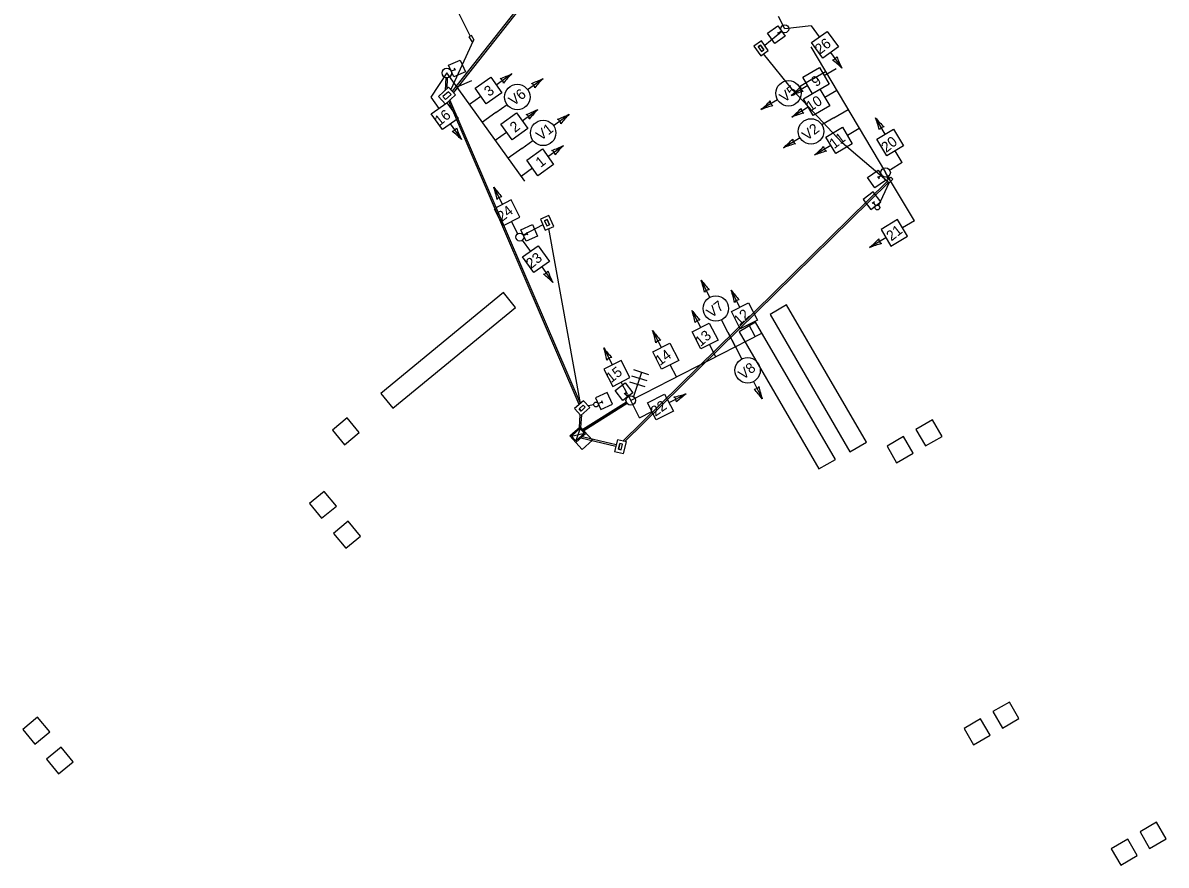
# Model space of a CAD drawing. Extents: x 995948 to 996893, y 1982239 to 1983420.
# Drawn here: x 996486.3 to 996846.1, y 1982238.6 to 1982503.8 of the extents above; entities that cross this region are included whole.
import ezdxf

# ---------------------------------------------------------------- set-up
doc = ezdxf.new("R2010")
doc.units = 0
for name, color, linetype in [('S_CURB', 7, 'Continuous'), ('S_DRIVEWAY', 7, 'Continuous'), ('S_EDGE_PAVEMENT', 7, 'Continuous'), ('S_PARKING', 7, 'Continuous'), ('S_PAVEMENT_CROWN', 7, 'Continuous'), ('S_SHOULDER', 7, 'Continuous'), ('S_SIDEWALK', 7, 'Continuous'), ('S_WALL', 7, 'Continuous')]:
    doc.layers.add(name, color=color, linetype=linetype)

msp = doc.modelspace()

# ---------------------------------------------------------------- linework, layer by layer
at = {"layer": 'S_CURB'}
for p, q in [((996658.48, 1982373.75), (996661.69, 1982376.65)), ((996665.53, 1982372.38), (996661.69, 1982376.65)), ((996662.32, 1982369.49), (996658.48, 1982373.75)), ((996658.94, 1982373.73), (996661.67, 1982376.18)), ((996660.33, 1982372.18), (996658.94, 1982373.73)), ((996658.96, 1982373.74), (996663.06, 1982374.64)), ((996660.31, 1982371.72), (996663.53, 1982374.61)), ((996661.67, 1982376.18), (996660.33, 1982372.19)), ((996660.33, 1982372.18), (996663.06, 1982374.64)), ((996663.06, 1982374.64), (996661.67, 1982376.18)), ((996662.32, 1982369.49), (996665.53, 1982372.38))]:
    msp.add_line(p, q, dxfattribs=at)
at = {"layer": 'S_DRIVEWAY'}
for p, q in [((996682.34, 1982559.39), (996621.37, 1982482.35)), ((996682.97, 1982559.38), (996621.8, 1982481.88)), ((996621.13, 1982511.73), (996627.07, 1982499.65)), ((996725.15, 1982501.15), (996719.78, 1982496.69)), ((996627.98, 1982498.16), (996620.96, 1982482.8)), ((996619.37, 1982486.58), (996619.15, 1982482.55)), ((996619.87, 1982486.55), (996619.68, 1982483.03)), ((996661.4, 1982383.66), (996620.32, 1982479.2)), ((996661.79, 1982384.01), (996620.71, 1982479.55)), ((996758.36, 1982453.88), (996675.15, 1982372.13)), ((996758.71, 1982453.52), (996675.72, 1982371.99)), ((996758.85, 1982453.37), (996755.56, 1982446.34)), ((996758.26, 1982455.25), (996758.66, 1982454.46)), ((996758.71, 1982455.48), (996759.04, 1982454.82)), ((996649.96, 1982440.21), (996643.79, 1982436.96)), ((996661.81, 1982384.02), (996651.81, 1982439.06)), ((996676.23, 1982384.36), (996662.48, 1982375.78)), ((996676.34, 1982384.14), (996662.65, 1982375.59)), ((996676.49, 1982383.94), (996662.82, 1982375.4)), ((996661.43, 1982376.42), (996661.67, 1982380.45)), ((996661.93, 1982376.39), (996662.17, 1982380.41)), ((996665.94, 1982383.54), (996664.17, 1982383.28)), ((996672.91, 1982370.48), (996661.86, 1982373.11)), ((996673.02, 1982370.97), (996662.31, 1982373.52))]:
    msp.add_line(p, q, dxfattribs=at)
msp.add_lwpolyline([(996758.22, 1982454.03), (996744.12, 1982466.06), (996728.69, 1982482.57), (996719.38, 1982494.02)], dxfattribs=at)
at = {"layer": 'S_EDGE_PAVEMENT'}
for p, q in [((996734.34, 1982496.24), (996757.83, 1982456.69)), ((996644.28, 1982453.98), (996619.7, 1982488.04)), ((996718.54, 1982405.93), (996677.61, 1982384.93))]:
    msp.add_line(p, q, dxfattribs=at)
for centre, radius in [((996726.11, 1982501.95), 1.25), ((996619.7, 1982488.04), 1.5), ((996757.83, 1982456.69), 1.5), ((996755.24, 1982445.66), 0.75), ((996642.69, 1982436.37), 1.25), ((996666.68, 1982383.65), 0.75), ((996677.61, 1982384.93), 1.5)]:
    msp.add_circle(centre, radius, dxfattribs=at)
at = {"layer": 'S_PARKING'}
for points in [[(996637.55, 1982418.87), (996598.91, 1982387.13), (996602.72, 1982382.5), (996641.36, 1982414.23)], [(996751.77, 1982371.76), (996726.65, 1982415), (996721.46, 1982411.98), (996746.58, 1982368.75)], [(996742.03, 1982366.37), (996716.91, 1982409.6), (996711.72, 1982406.59), (996736.84, 1982363.36)], [(996588.34, 1982379.44), (996583.7, 1982375.63), (996587.51, 1982370.99), (996592.15, 1982374.8)], [(996767.39, 1982375.81), (996770.4, 1982370.62), (996775.59, 1982373.63), (996772.58, 1982378.82)], [(996758.3, 1982370.52), (996761.31, 1982365.34), (996766.5, 1982368.35), (996763.49, 1982373.54)], [(996581.14, 1982356.27), (996576.51, 1982352.46), (996580.31, 1982347.82), (996584.95, 1982351.63)], [(996588.7, 1982346.88), (996584.06, 1982343.07), (996587.87, 1982338.44), (996592.51, 1982342.24)], [(996791.62, 1982286.95), (996794.64, 1982281.77), (996799.82, 1982284.78), (996796.81, 1982289.97)], [(996490.9, 1982285.18), (996486.26, 1982281.37), (996490.07, 1982276.74), (996494.7, 1982280.55)], [(996782.53, 1982281.67), (996785.55, 1982276.48), (996790.73, 1982279.5), (996787.72, 1982284.69)], [(996498.31, 1982275.78), (996493.67, 1982271.98), (996497.48, 1982267.34), (996502.12, 1982271.15)], [(996837.93, 1982249.1), (996840.95, 1982243.91), (996846.14, 1982246.92), (996843.12, 1982252.11)], [(996828.84, 1982243.81), (996831.86, 1982238.63), (996837.05, 1982241.64), (996834.03, 1982246.83)]]:
    msp.add_lwpolyline(points, close=True, dxfattribs=at)
at = {"layer": 'S_PAVEMENT_CROWN'}
for p, q in [((996726.11, 1982501.95), (996724.12, 1982505.82)), ((996734.42, 1982502.9), (996726.11, 1982501.95)), ((996734.42, 1982502.9), (996736.96, 1982499.37)), ((996740.52, 1982494.46), (996744.05, 1982489.56)), ((996742.27, 1982489.38), (996738.53, 1982487.17)), ((996619.7, 1982488.04), (996614.7, 1982480.42)), ((996635.29, 1982484.3), (996640.19, 1982487.83)), ((996645.15, 1982482.81), (996650.07, 1982486.35)), ((996734.41, 1982485.88), (996730.69, 1982483.67)), ((996733.32, 1982484.06), (996728.12, 1982480.98)), ((996742.45, 1982482.54), (996738.71, 1982480.33)), ((996614.7, 1982480.42), (996617.24, 1982476.89)), ((996626.84, 1982478.21), (996630.37, 1982480.75)), ((996635.14, 1982475.6), (996638.66, 1982478.13)), ((996723.81, 1982479.59), (996718.59, 1982476.5)), ((996643.43, 1982472.99), (996648.33, 1982476.51)), ((996653.29, 1982471.49), (996658.21, 1982475.04)), ((996733.5, 1982477.23), (996728.3, 1982474.15)), ((996741.51, 1982473.89), (996737.79, 1982471.68)), ((996757.72, 1982468.74), (996754.62, 1982473.93)), ((996620.8, 1982471.98), (996624.33, 1982467.08)), ((996749.55, 1982470.55), (996745.81, 1982468.33)), ((996634.98, 1982466.9), (996638.51, 1982469.44)), ((996643.28, 1982464.29), (996646.79, 1982466.82)), ((996730.91, 1982467.6), (996725.69, 1982464.51)), ((996651.54, 1982461.7), (996656.45, 1982465.23)), ((996740.6, 1982465.24), (996735.4, 1982462.16)), ((996763.07, 1982459.81), (996760.84, 1982463.54)), ((996763.07, 1982459.81), (996759.33, 1982457.58)), ((996643.11, 1982455.6), (996646.64, 1982458.14)), ((996766.89, 1982441.48), (996757.83, 1982456.69)), ((996637.28, 1982446.7), (996634.51, 1982452.07)), ((996766.89, 1982441.48), (996763.16, 1982439.25)), ((996642.02, 1982437.43), (996640.03, 1982441.3)), ((996643.47, 1982435.4), (996646.01, 1982431.87)), ((996757.95, 1982436.16), (996752.76, 1982433.06)), ((996649.57, 1982426.96), (996653.1, 1982422.06)), ((996702.55, 1982417.44), (996699.77, 1982422.83)), ((996711.99, 1982414.27), (996709.24, 1982419.65)), ((996699.62, 1982407.92), (996696.87, 1982413.3)), ((996708.19, 1982406.48), (996706.21, 1982410.33)), ((996687.25, 1982401.57), (996684.49, 1982406.95)), ((996716.76, 1982405.02), (996714.78, 1982408.88)), ((996704.39, 1982398.67), (996702.41, 1982402.54)), ((996710.58, 1982401.83), (996712.56, 1982397.98)), ((996671.87, 1982396.13), (996669.11, 1982401.5)), ((996692.01, 1982392.32), (996690.03, 1982396.19)), ((996676.62, 1982386.87), (996674.63, 1982390.73)), ((996716.21, 1982390.86), (996718.98, 1982385.47)), ((996676.62, 1982386.87), (996677.61, 1982384.93)), ((996680.4, 1982379.51), (996677.61, 1982384.93)), ((996689.66, 1982384.27), (996695.04, 1982387.02)), ((996680.4, 1982379.51), (996684.27, 1982381.49))]:
    msp.add_line(p, q, dxfattribs=at)
for points in [[(996734.51, 1982497.61), (996739.43, 1982501.15), (996742.97, 1982496.23), (996738.05, 1982492.68)], [(996736.99, 1982489.76), (996740.08, 1982484.54), (996734.86, 1982481.45), (996731.77, 1982486.67)], [(996632.14, 1982478.29), (996628.6, 1982483.21), (996633.52, 1982486.75), (996637.06, 1982481.83)], [(996737.16, 1982482.93), (996740.25, 1982477.72), (996735.04, 1982474.63), (996731.95, 1982479.85)], [(996614.79, 1982475.13), (996619.72, 1982478.67), (996623.26, 1982473.75), (996618.33, 1982470.21)], [(996640.28, 1982466.98), (996636.74, 1982471.9), (996641.66, 1982475.44), (996645.2, 1982470.52)], [(996744.26, 1982470.94), (996747.35, 1982465.72), (996742.14, 1982462.64), (996739.05, 1982467.85)], [(996763.43, 1982465.09), (996758.22, 1982461.98), (996755.12, 1982467.19), (996760.33, 1982470.3)], [(996648.4, 1982455.69), (996644.86, 1982460.61), (996649.78, 1982464.15), (996653.32, 1982459.23)], [(996637.35, 1982439.91), (996642.74, 1982442.69), (996639.97, 1982448.08), (996634.57, 1982445.31)], [(996764.71, 1982436.66), (996761.6, 1982441.87), (996756.39, 1982438.75), (996759.51, 1982433.55)], [(996643.56, 1982430.11), (996648.48, 1982433.65), (996652.02, 1982428.73), (996647.1, 1982425.19)], [(996717.47, 1982410.26), (996712.07, 1982407.49), (996709.3, 1982412.89), (996714.7, 1982415.66)], [(996705.09, 1982403.91), (996699.69, 1982401.15), (996696.93, 1982406.54), (996702.33, 1982409.31)], [(996692.72, 1982397.56), (996687.32, 1982394.8), (996684.56, 1982400.19), (996689.95, 1982402.96)], [(996671.95, 1982389.35), (996677.34, 1982392.13), (996674.56, 1982397.52), (996669.17, 1982394.74)], [(996685.65, 1982378.8), (996682.89, 1982384.2), (996688.28, 1982386.96), (996691.04, 1982381.56)]]:
    msp.add_lwpolyline(points, close=True, dxfattribs=at)
for centre in [(996727.25, 1982481.63), (996641.9, 1982480.47), (996650.04, 1982469.16), (996734.35, 1982469.64), (996704.38, 1982413.88), (996714.38, 1982394.42)]:
    msp.add_circle(centre, 4, dxfattribs=at)
for centre, radius, start, end in [((996740.97, 1982493.83), 1.63, 273.8828, 337.5774), ((996722.97, 1982468.96), 29.47, 44.3384, 52.0765), ((996770.28, 1982502.99), 29.47, 199.3837, 207.1218), ((996626.76, 1982514.06), 29.47, 289.381, 297.1192), ((996635.92, 1982484.75), 1.63, 3.8802, 67.5748), ((996660.79, 1982466.75), 29.47, 134.3358, 142.0739), ((996636.62, 1982512.57), 29.47, 289.4116, 297.1497), ((996645.8, 1982483.27), 1.63, 3.9107, 67.6053), ((996670.68, 1982465.28), 29.47, 134.3663, 142.1045), ((996709.48, 1982503.81), 29.47, 309.236, 316.9741), ((996739.17, 1982453.66), 29.47, 104.2813, 112.0194), ((996732.65, 1982483.66), 1.63, 178.7804, 242.475), ((996699.94, 1982499.32), 29.47, 309.2666, 317.0047), ((996729.65, 1982449.19), 29.47, 104.3118, 112.05), ((996723.12, 1982479.19), 1.63, 178.811, 242.5056), ((996634.89, 1982502.75), 29.47, 289.381, 297.1192), ((996644.05, 1982473.44), 1.63, 3.8802, 67.5748), ((996668.93, 1982455.43), 29.47, 134.3358, 142.0739), ((996644.76, 1982501.26), 29.47, 289.4116, 297.1497), ((996678.82, 1982453.97), 29.47, 134.3663, 142.1045), ((996709.66, 1982496.98), 29.47, 309.236, 316.9741), ((996739.35, 1982446.83), 29.47, 104.2813, 112.0194), ((996732.83, 1982476.84), 1.63, 178.7804, 242.475), ((996777.4, 1982492.64), 29.47, 219.4006, 227.1387), ((996727.34, 1982462.8), 29.47, 14.4459, 22.184), ((996621.25, 1982471.35), 1.63, 273.8828, 337.5774), ((996650.56, 1982480.51), 29.47, 199.3837, 207.1218), ((996653.93, 1982471.96), 1.63, 3.9107, 67.6053), ((996757.32, 1982469.41), 1.63, 88.945, 152.6396), ((996603.25, 1982446.48), 29.47, 44.3384, 52.0765), ((996707.03, 1982487.33), 29.47, 309.2666, 317.0047), ((996730.22, 1982467.2), 1.63, 178.811, 242.5056), ((996643.01, 1982491.46), 29.47, 289.381, 297.1192), ((996652.17, 1982462.15), 1.63, 3.8802, 67.5748), ((996677.05, 1982444.15), 29.47, 134.3358, 142.0739), ((996736.75, 1982437.19), 29.47, 104.3118, 112.05), ((996716.76, 1982484.99), 29.47, 309.236, 316.9741), ((996746.45, 1982434.84), 29.47, 104.2813, 112.0194), ((996739.93, 1982464.84), 1.63, 178.7804, 242.475), ((996606.58, 1982442.65), 29.47, 10.8925, 18.6306), ((996658.4, 1982469.33), 29.47, 215.8473, 223.5854), ((996636.92, 1982447.38), 1.63, 85.3916, 149.0863), ((996734.02, 1982455.81), 29.47, 309.4816, 317.2197), ((996763.93, 1982405.78), 29.47, 104.5268, 112.2649), ((996757.28, 1982435.76), 1.63, 179.0259, 242.7206), ((996650.02, 1982426.33), 1.63, 273.8828, 337.5774), ((996632.02, 1982401.46), 29.47, 44.3384, 52.0765), ((996679.33, 1982435.5), 29.47, 199.3837, 207.1218), ((996723.66, 1982440.09), 29.47, 215.8477, 223.5859), ((996671.84, 1982413.42), 29.47, 10.893, 18.6311), ((996702.18, 1982418.15), 1.63, 85.3921, 149.0867), ((996733.17, 1982436.86), 29.47, 215.7298, 223.468), ((996681.29, 1982410.29), 29.47, 10.7751, 18.5132), ((996711.64, 1982414.96), 1.63, 85.2742, 148.9688), ((996720.79, 1982430.51), 29.47, 215.7298, 223.468), ((996668.92, 1982403.94), 29.47, 10.7751, 18.5132), ((996699.27, 1982408.61), 1.63, 85.2742, 148.9688), ((996708.42, 1982424.16), 29.47, 215.7298, 223.468), ((996656.55, 1982397.59), 29.47, 10.7751, 18.5132), ((996686.9, 1982402.26), 1.63, 85.2742, 148.9688), ((996641.18, 1982392.09), 29.47, 10.8925, 18.6306), ((996693, 1982418.76), 29.47, 215.8473, 223.5854), ((996671.52, 1982396.82), 1.63, 85.3916, 149.0863), ((996716.57, 1982390.15), 1.63, 265.3183, 329.0129), ((996695.07, 1982368.24), 29.47, 35.7739, 43.512), ((996746.92, 1982394.85), 29.47, 190.8192, 198.5573), ((996685.7, 1982414.98), 29.47, 280.7306, 288.4687), ((996690.35, 1982384.62), 1.63, 355.2297, 58.9243), ((996712.23, 1982363.08), 29.47, 125.6853, 133.4234)]:
    msp.add_arc(centre, radius, start, end, dxfattribs=at)
at = {"layer": 'S_SHOULDER'}
msp.add_line((996623.01, 1982483.69), (996627.58, 1982485.72), dxfattribs=at)
for points in [[(996726.23, 1982499.6), (996722.96, 1982497.3), (996720.66, 1982500.58), (996723.94, 1982502.88)], [(996620.26, 1982490.48), (996623.92, 1982492.1), (996625.54, 1982488.45), (996621.89, 1982486.82)], [(996757.75, 1982454.19), (996754.47, 1982451.89), (996752.18, 1982455.17), (996755.45, 1982457.47)], [(996756.37, 1982447.48), (996753.92, 1982450.64), (996750.75, 1982448.19), (996753.2, 1982445.03)], [(996643.02, 1982438.7), (996646.67, 1982440.33), (996648.3, 1982436.67), (996644.64, 1982435.05)], [(996668.18, 1982382.13), (996671.84, 1982383.75), (996670.21, 1982387.41), (996666.56, 1982385.78)], [(996675.11, 1982384.89), (996672.66, 1982388.06), (996675.83, 1982390.51), (996678.28, 1982387.34)]]:
    msp.add_lwpolyline(points, close=True, dxfattribs=at)
at = {"layer": 'S_SIDEWALK'}
for p, q in [((996627.46, 1982499.89), (996626.68, 1982499.41)), ((996626.68, 1982499.41), (996627.58, 1982497.92)), ((996628.37, 1982498.39), (996627.46, 1982499.89)), ((996723.76, 1982500.84), (996724.26, 1982500.12)), ((996725.09, 1982501.24), (996724.01, 1982500.48)), ((996627.58, 1982497.92), (996628.37, 1982498.39)), ((996718.75, 1982498.16), (996716.36, 1982496.48)), ((996716.36, 1982496.48), (996718.51, 1982493.41)), ((996717.75, 1982496.23), (996718.5, 1982496.76)), ((996718.5, 1982496.76), (996717.75, 1982496.23)), ((996717.75, 1982496.23), (996718.75, 1982494.8)), ((996717.75, 1982496.23), (996718.75, 1982494.8)), ((996718.5, 1982496.76), (996719.51, 1982495.33)), ((996719.51, 1982495.33), (996718.5, 1982496.76)), ((996720.9, 1982495.08), (996718.75, 1982498.16)), ((996718.51, 1982493.41), (996720.9, 1982495.08)), ((996718.75, 1982494.8), (996719.51, 1982495.33)), ((996718.75, 1982494.8), (996719.51, 1982495.33)), ((996621.07, 1982488.65), (996622.28, 1982489.18)), ((996622.45, 1982488.79), (996622.1, 1982489.58)), ((996734.41, 1982485.88), (996738.9, 1982488.54)), ((996620.27, 1982483.57), (996617.06, 1982480.66)), ((996620.2, 1982482.15), (996618.47, 1982480.59)), ((996619.25, 1982478.23), (996622.47, 1982481.14)), ((996619.32, 1982479.65), (996621.05, 1982481.21)), ((996621.05, 1982481.21), (996620.2, 1982482.15)), ((996622.47, 1982481.14), (996620.27, 1982483.57)), ((996617.06, 1982480.66), (996619.25, 1982478.23)), ((996618.47, 1982480.59), (996619.32, 1982479.65)), ((996635.14, 1982475.6), (996630.91, 1982472.55)), ((996741.51, 1982473.89), (996746, 1982476.55)), ((996643.28, 1982464.29), (996639.05, 1982461.24)), ((996756.6, 1982455.83), (996755.52, 1982455.07)), ((996755.27, 1982455.43), (996755.77, 1982454.71)), ((996759.48, 1982455.24), (996758.22, 1982454.03)), ((996758.22, 1982454.03), (996758.85, 1982453.37)), ((996758.85, 1982453.37), (996760.12, 1982454.58)), ((996760.12, 1982454.58), (996759.48, 1982455.24)), ((996753.63, 1982447.03), (996754.32, 1982447.56)), ((996754.78, 1982446.25), (996753.98, 1982447.29)), ((996651.84, 1982443.18), (996649.17, 1982441.99)), ((996649.17, 1982441.99), (996650.7, 1982438.56)), ((996650.49, 1982441.48), (996651.33, 1982441.86)), ((996651.33, 1982441.86), (996650.49, 1982441.48)), ((996650.49, 1982441.48), (996651.2, 1982439.88)), ((996650.49, 1982441.48), (996651.2, 1982439.88)), ((996651.33, 1982441.86), (996652.04, 1982440.26)), ((996652.04, 1982440.26), (996651.33, 1982441.86)), ((996653.36, 1982439.75), (996651.84, 1982443.18)), ((996645.21, 1982437.01), (996644.86, 1982437.81)), ((996650.7, 1982438.56), (996653.36, 1982439.75)), ((996651.2, 1982439.88), (996652.04, 1982440.26)), ((996651.2, 1982439.88), (996652.04, 1982440.26)), ((996643.83, 1982436.88), (996645.03, 1982437.41)), ((996708.19, 1982406.48), (996710.58, 1982401.84)), ((996710.58, 1982401.83), (996708.2, 1982406.47)), ((996676.23, 1982387.43), (996675.54, 1982386.89)), ((996662.73, 1982384.86), (996659.95, 1982382.35)), ((996664.69, 1982382.7), (996662.73, 1982384.86)), ((996667.37, 1982383.96), (996668.57, 1982384.49)), ((996668.39, 1982384.89), (996668.75, 1982384.09)), ((996676.69, 1982386.12), (996675.89, 1982387.16)), ((996659.95, 1982382.35), (996661.91, 1982380.18)), ((996661.37, 1982382.28), (996662.66, 1982383.45)), ((996662.66, 1982383.45), (996661.37, 1982382.28)), ((996661.98, 1982381.59), (996661.37, 1982382.28)), ((996661.37, 1982382.28), (996661.98, 1982381.59)), ((996661.91, 1982380.18), (996664.69, 1982382.7)), ((996661.98, 1982381.59), (996663.28, 1982382.77)), ((996661.98, 1982381.59), (996663.28, 1982382.77)), ((996663.28, 1982382.77), (996662.66, 1982383.45)), ((996663.28, 1982382.77), (996662.66, 1982383.45)), ((996673.4, 1982372.55), (996672.53, 1982368.9)), ((996676.24, 1982371.87), (996673.4, 1982372.55)), ((996673.73, 1982369.64), (996674.14, 1982371.34)), ((996674.14, 1982371.34), (996673.73, 1982369.64)), ((996674.63, 1982369.43), (996673.73, 1982369.64)), ((996673.73, 1982369.64), (996674.63, 1982369.43)), ((996675.04, 1982371.13), (996674.14, 1982371.34)), ((996675.04, 1982371.13), (996674.14, 1982371.34)), ((996674.63, 1982369.43), (996675.04, 1982371.13)), ((996674.63, 1982369.43), (996675.04, 1982371.13)), ((996675.37, 1982368.22), (996676.24, 1982371.87)), ((996672.53, 1982368.9), (996675.37, 1982368.22))]:
    msp.add_line(p, q, dxfattribs=at)
at = {"layer": 'S_WALL'}
for p, q in [((996682.73, 1982391.08), (996677.98, 1982392.63)), ((996680.97, 1982393.76), (996678.49, 1982386.15)), ((996683.35, 1982392.98), (996678.6, 1982394.53)), ((996682.11, 1982389.18), (996677.35, 1982390.73))]:
    msp.add_line(p, q, dxfattribs=at)

# ---------------------------------------------------------------- texts
at = {"layer": 'S_PAVEMENT_CROWN'}
for s, rotation, p in [('26', 38.2735, (996737.17, 1982493.75)), ('9', 38.2735, (996735.98, 1982483.51)), ('3', 38.2735, (996633.04, 1982480.45)), ('V6', 37.9434, (996640.75, 1982477.53)), ('V5', 38.3362, (996726.01, 1982478.59)), ('10', 33.4103, (996734.15, 1982475.79)), ('16', 38.2735, (996617.45, 1982471.27)), ('2', 38.2735, (996641.16, 1982469.12)), ('V1', 37.8707, (996649.34, 1982466.57)), ('V2', 38.3358, (996733.1, 1982466.59)), ('11', 37.1602, (996741.63, 1982464.01)), ('20', 38.2735, (996758.03, 1982462.83)), ('1', 38.2735, (996649.25, 1982458.12)), ('24', 38.2735, (996637.08, 1982441.08)), ('21', 38.2735, (996759.65, 1982434.95)), ('23', 38.2735, (996646.23, 1982426.27)), ('V7', 38.2735, (996703.05, 1982410.77)), ('12', 42.247, (996711.78, 1982408.37)), ('13', 41.3717, (996699.62, 1982401.74)), ('14', 36.4629, (996686.8, 1982395.75)), ('15', 38.2735, (996671.44, 1982390.33)), ('V8', 38.2735, (996713.06, 1982391.31)), ('22', 35.561, (996685.35, 1982379.75))]:
    msp.add_text(s, height=3.25, rotation=rotation, dxfattribs=at).set_placement(p)

doc.saveas('drawing.dxf')
